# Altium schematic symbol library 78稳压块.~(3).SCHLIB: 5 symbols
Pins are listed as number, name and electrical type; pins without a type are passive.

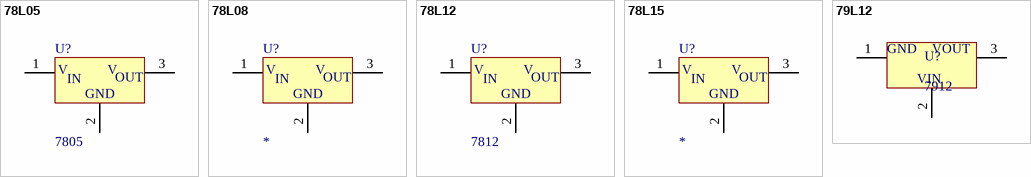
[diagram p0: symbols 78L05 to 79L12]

## 78L05
designator U?, comment 7805
3-Terminal Positive Voltage Regulator
footprint VR5
simulation model 78L05 (SUBCKT)
pins: 1 VIN, 2 GND, 3 VOUT

## 78L08
designator U?
3-Terminal Positive Voltage Regulator
footprint 78XX
simulation model 78L08 (SUBCKT)
pins: 1 VIN, 2 GND, 3 VOUT

## 78L12
designator U?, comment 7812
3-Terminal Positive Voltage Regulator
footprint VR5
simulation model 78L12 (SUBCKT)
pins: 1 VIN, 2 GND, 3 VOUT

## 78L15
designator U?
3-Terminal Positive Voltage Regulator
footprint 78XX
simulation model 78L15 (SUBCKT)
pins: 1 VIN, 2 GND, 3 VOUT

## 79L12
designator U?, comment 7912
pins: 1 VIN, 2 GND, 3 VOUT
